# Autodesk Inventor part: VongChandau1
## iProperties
Created: 2011-05
Part Number: VongChandau1
Document SubType Name: Modeling
Designer: 904Chiaki
Density: 1 g/cm^3
Author: 904Chiaki
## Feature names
1. Revolution1
